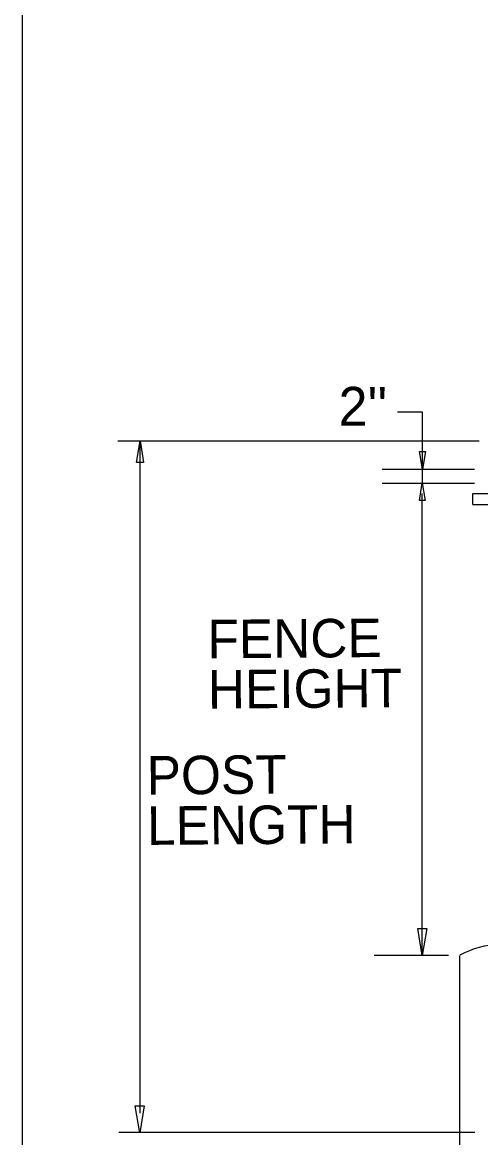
# Model space of a CAD drawing. Extents: x 0 to 1270, y 0 to 830.
# Drawn here: x 0 to 58.4, y 576.5 to 718.6 of the extents above; entities that cross this region are included whole.
import ezdxf

# ---------------------------------------------------------------- set-up
doc = ezdxf.new("R2010")
doc.units = 0
for name, color, linetype in [('CT_Border_Perimeter_Shape', 7, 'Continuous'), ('CT_Dimensions', 7, 'Continuous'), ('CT_Title_Block_Text', 7, 'Continuous'), ('sb_Existing Concrete', 7, 'Continuous'), ('sb_Existing Structural Steel', 7, 'Continuous')]:
    doc.layers.add(name, color=color, linetype=linetype)

# ---------------------------------------------------------------- blocks, each defined once
blk = doc.blocks.new('BDR_CTDOT_Standards')
at = {"layer": 'CT_Border_Perimeter_Shape'}
blk.add_lwpolyline([(0, 0), (1270, 0), (1270, 830), (0, 830)], close=True, dxfattribs=at)

msp = doc.modelspace()

# ---------------------------------------------------------------- linework, layer by layer
at = {"layer": 'CT_Dimensions'}
for p, q in [((51.03, 668.95), (47.81, 668.95)), ((51.01, 659.78), (51.01, 668.97)), ((12.18, 665.3), (58.25, 665.3)), ((15.02, 579.67), (15.02, 664.93)), ((45.88, 661.72), (57.63, 661.72)), ((45.87, 659.92), (57.63, 659.92)), ((50.98, 599.8), (50.98, 658.61)), ((44.87, 599.8), (54.34, 599.8)), ((12.32, 577.25), (57.67, 577.25))]:
    msp.add_line(p, q, dxfattribs=at)
for points in [[(14.55, 662.55), (15.01, 665.3), (15.47, 662.55)], [(51.38, 663.93), (51.01, 661.71), (50.63, 663.93)], [(50.62, 657.7), (50.99, 659.93), (51.36, 657.7)], [(51.55, 603.18), (50.98, 599.75), (50.41, 603.18)], [(15.55, 580.6), (14.98, 577.17), (14.41, 580.6)]]:
    msp.add_lwpolyline(points, close=True, dxfattribs=at)
at = {"layer": 'sb_Existing Concrete'}
msp.add_line((55.79, 573.96), (55.78, 599.77), dxfattribs=at)
msp.add_arc((60.81, 590.96), 10.15, 59.953, 119.6876, dxfattribs=at)
at = {"layer": 'sb_Existing Structural Steel'}
for p, q in [((57.43, 658.58), (66.72, 658.58)), ((57.43, 657.2), (57.43, 658.58)), ((57.43, 657.2), (66.72, 657.2))]:
    msp.add_line(p, q, dxfattribs=at)

# ---------------------------------------------------------------- block references
at = {"layer": 'CT_Title_Block_Text'}
msp.add_blockref('BDR_CTDOT_Standards', (0, 0), dxfattribs=at)

# ---------------------------------------------------------------- texts
at = {"layer": 'CT_Dimensions'}
for s, height, rotation, p in [("2'' ", 4.95, 360, (40.32, 667.23)), ('FENCE ', 4.901, 0.4256, (23.62, 637.61)), ('HEIGHT', 4.901, 0.4256, (23.67, 631.2)), ('POST', 4.901, 0.4256, (15.87, 620.25)), ('LENGTH', 4.901, 0.4256, (15.92, 613.84))]:
    msp.add_text(s, height=height, rotation=rotation, dxfattribs=at).set_placement(p)

doc.saveas('drawing.dxf')
